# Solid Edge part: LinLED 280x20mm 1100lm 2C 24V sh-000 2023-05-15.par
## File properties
Author: jaroslaw.przewlocki
Template: iso metric part.par
Last saved by: jaroslaw.przewlocki
Revision: 1
Application: Solid Edge
Gęstość: 0,000 kg/m^3
Dokładność: 0,990
Username: jaroslaw.przewlocki
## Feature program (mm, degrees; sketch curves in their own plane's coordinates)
body "unnamed Body 1"
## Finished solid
Body 1: solid body, 1038 faces, 2686 edges, 1732 vertices.
  Faces by surface: plane 733, cylinder 149, torus 64, cone 50, spline 26, sphere 16
  Edges by curve: line 2040, curve on surface 356, circle 188, ellipse 66, spline 36
Bounding box of the edges (mm; curved faces can reach further): 279.600 x 20.000 x 4.450, from (-139.8, -10, -1) to (139.8, 10, 3.45).
Cylindrical faces by radius (mm): R0.2 x46, R0.2169 x6, R0.25 x22, R0.3373 x6, R0.4 x8, R0.4006 x2, R0.4008 x2, R0.525 x2, R0.6 x20, R1 x12, R1.1 x4, R1.1989 x2, R1.199 x2, R1.2 x10, R2.15 x5
Conical faces (half-angle, radius in mm at the cone's reference point): 0.398 deg R1.1964 x2, 0.4493 deg R1.1964 x2, 0.4746 deg R1.1948 x2, 0.4758 deg R1.1948 x2, 0.5 deg R0.5056 x4, 0.5 deg R1.0082 x4, 1 deg R0.5511 x2, 10 deg R0.2132 x4, 10 deg R0.4132 x4, 16.0099 deg R1.1053 x2, 16.1249 deg R1.1279 x2, 18.8604 deg R1.0669 x4, 19.5041 deg R0.5138 x2, 19.8244 deg R0.5099 x2, 27.363 deg R0.6214 x2, 40.6434 deg R0.5161 x2, 43.3309 deg R0.4892 x2, 45 deg R0.575 x2, 45 deg R0.625 x4
Toroidal faces (ring radius, tube radius in mm): R0.0958 r0.3997 x4, R0.1076 r0.4 x2, R0.1101 r0.4001 x2, R0.1217 r0.4 x2, R0.1234 r0.4 x2, R0.1626 r0.228 x2, R0.1634 r0.2287 x2, R0.3287 r0.2001 x2, R0.3684 r0.2151 x2, R0.3703 r0.4 x2, R0.3818 r0.2 x4, R0.4166 r0.3983 x2, R0.5981 r0.197 x2, R0.5982 r0.197 x2, R0.6009 r0.3968 x2, R0.6009 r0.3969 x2, R0.6227 r0.2 x2, R0.6235 r0.2 x2, R0.8 r0.2 x4, R0.8522 r0.3 x2, R0.9002 r0.2 x2, R0.9018 r0.2 x2, R0.9197 r0.223 x2, R0.9365 r0.2 x2, R0.9663 r0.2263 x2, R0.9665 r0.2263 x2, R1.429 r1.2 x2, R1.8741 r0.2175 x2, R1.9007 r0.2 x2
Spherical faces by radius (mm): R0.2 x12, R0.6 x4
Planar faces by outward normal: +x 85, +y 88, +z 121, -x 85, -y 89, -z 9, oblique 256
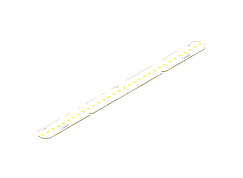
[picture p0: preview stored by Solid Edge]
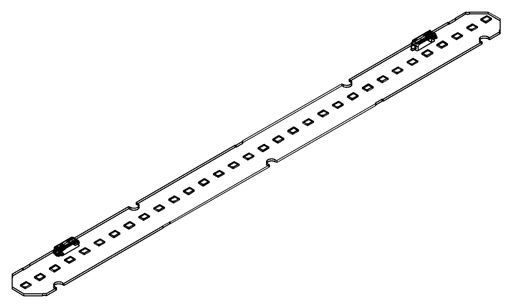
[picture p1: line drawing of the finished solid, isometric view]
